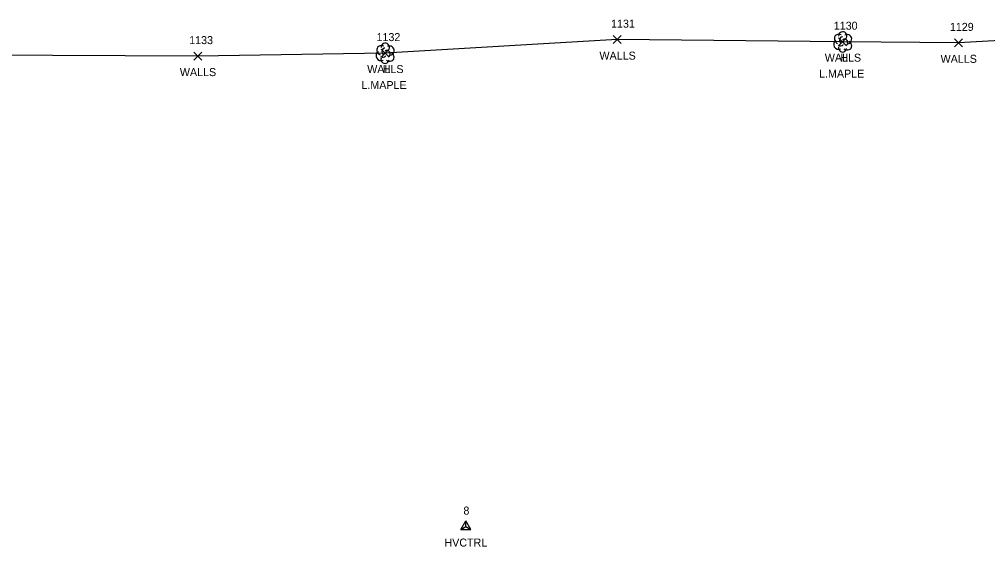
# Model space of a CAD drawing. Extents: x 1519347 to 1522636, y 378779 to 379832.
# Drawn here: x 1521885.3 to 1522127.4, y 378778.8 to 378910.7 of the extents above; entities that cross this region are included whole.
import ezdxf

# ---------------------------------------------------------------- set-up
doc = ezdxf.new("R2010")
doc.units = 0
for name, color, linetype in [('C_A', 7, 'Continuous'), ('C_I', 7, 'Continuous'), ('CPSM', 7, 'Continuous'), ('L_A', 7, 'Continuous'), ('L_C', 7, 'Continuous'), ('L_I', 7, 'Continuous'), ('L_TIC', 7, 'Continuous'), ('LTD', 7, 'Continuous'), ('LWS', 7, 'Continuous')]:
    doc.layers.add(name, color=color, linetype=linetype)

msp = doc.modelspace()

# ---------------------------------------------------------------- linework, layer by layer
at = {"layer": 'CPSM'}
for p, q in [((1521995.64, 378783.1), (1521996.89, 378785.27)), ((1521995.64, 378783.1), (1521996.89, 378783.82)), ((1521998.14, 378783.1), (1521996.89, 378785.27)), ((1521996.89, 378783.82), (1521996.89, 378785.27)), ((1521996.89, 378783.82), (1521996.89, 378783.82)), ((1521996.89, 378783.82), (1521998.14, 378783.1)), ((1521995.64, 378783.1), (1521998.14, 378783.1))]:
    msp.add_line(p, q, dxfattribs=at)
at = {"layer": 'L_TIC'}
for points in [[(1522033.79, 378904.64), (1522035.79, 378906.64)], [(1522035.79, 378904.64), (1522033.79, 378906.64)], [(1522090.12, 378904.13), (1522092.12, 378906.13)], [(1522092.12, 378904.13), (1522090.12, 378906.13)], [(1522119.07, 378903.84), (1522121.07, 378905.84)], [(1522121.07, 378903.84), (1522119.07, 378905.84)], [(1521928.9, 378900.52), (1521930.9, 378902.52)], [(1521930.9, 378900.52), (1521928.9, 378902.52)], [(1521975.72, 378901.28), (1521977.72, 378903.28)], [(1521977.72, 378901.28), (1521975.72, 378903.28)]]:
    msp.add_lwpolyline(points, dxfattribs=at)
at = {"layer": 'LTD'}
for p, q in [((1522091.12, 378905.13), (1522091.12, 378905.13)), ((1522091.12, 378905.13), (1522091.12, 378905.13)), ((1521976.72, 378902.28), (1521976.72, 378902.28)), ((1521976.72, 378902.28), (1521976.72, 378902.28))]:
    msp.add_line(p, q, dxfattribs=at)
for centre in [(1522091.16, 378906.56), (1521976.77, 378903.72)]:
    msp.add_arc(centre, 1.05, 335.5272, 180.9563, dxfattribs=at)
for centre, major_axis, ratio, start_param, end_param in [((1522090.33, 378905.79), (1.21, -0.51), 0.895232, 1.570796, 4.712389), ((1522092.16, 378905.71), (-1.14, -0.48), 0.949671, 1.570796, 4.712389), ((1522090.03, 378904.42), (0.58, -1.04), 0.959034, 3.141593, 6.283185), ((1522090.91, 378905.58), (-0.208, -0.792), 0.645439, 3.141593, 6.283185), ((1522091.62, 378904.96), (-0.5, 0.667), 0.989748, 3.141593, 6.283185), ((1522092.12, 378904.29), (-1.09, 0.79), 0.841452, 1.570796, 4.712389), ((1521975.64, 378901.57), (0.58, -1.04), 0.959034, 3.141593, 6.283185), ((1521975.93, 378902.95), (1.21, -0.51), 0.895232, 1.570796, 4.712389), ((1521976.51, 378902.74), (-0.208, -0.792), 0.645439, 3.141593, 6.283185), ((1521977.22, 378902.12), (-0.5, 0.667), 0.989748, 3.141593, 6.283185), ((1521977.72, 378901.45), (-1.09, 0.79), 0.841452, 1.570796, 4.712389), ((1521977.76, 378902.87), (-1.14, -0.48), 0.949671, 1.570796, 4.712389), ((1522091.12, 378903.63), (0.26, 1.06), 0.942809, 1.570796, 4.712389), ((1522090.66, 378904.38), (-0.625, -0.083), 0.423636, 0, 3.141593), ((1521976.72, 378900.78), (0.26, 1.06), 0.942809, 1.570796, 4.712389), ((1521976.26, 378901.53), (-0.625, -0.083), 0.423636, 0, 3.141593)]:
    msp.add_ellipse(centre, major_axis=major_axis, ratio=ratio, start_param=start_param, end_param=end_param, dxfattribs=at)
at = {"layer": 'LWS'}
msp.add_lwpolyline([(1522445.31, 378910.72), (1522401.54, 378910.43), (1522348.21, 378909.74), (1522295.88, 378908.39), (1522245.08, 378908.42), (1522202.2, 378906.68), (1522157.16, 378906.96), (1522120.07, 378904.84), (1522091.12, 378905.13), (1522034.79, 378905.64), (1521976.72, 378902.28), (1521929.9, 378901.52), (1521875.34, 378901.77), (1521835.92, 378899.64), (1521789.94, 378904.13), (1521732.75, 378904.41), (1521692.11, 378903.65), (1521648.67, 378903.93), (1521616.94, 378904.79), (1521567.34, 378904.32)], dxfattribs=at)

# ---------------------------------------------------------------- texts
at = {"layer": 'C_A'}
msp.add_text('HVCTRL', height=2, dxfattribs=at).set_placement((1521991.58, 378778.82))
at = {"layer": 'C_I'}
msp.add_text('8', height=2, dxfattribs=at).set_placement((1521996.32, 378786.82))
at = {"layer": 'L_A'}
for s, p in [('WALLS', (1522030.33, 378900.64)), ('WALLS', (1522086.66, 378900.13)), ('H', (1522090.55, 378900.13)), ('WALLS', (1522115.61, 378899.84)), ('WALLS', (1521925.44, 378896.52)), ('WALLS', (1521972.27, 378897.28)), ('H', (1521976.16, 378897.28))]:
    msp.add_text(s, height=2, dxfattribs=at).set_placement(p)
at = {"layer": 'L_C'}
for p in [(1522085.23, 378896.13), (1521970.83, 378893.28)]:
    msp.add_text('L.MAPLE', height=2, dxfattribs=at).set_placement(p)
at = {"layer": 'L_I'}
for s, p in [('1131', (1522033.23, 378908.64)), ('1130', (1522088.91, 378908.13)), ('1130', (1522088.91, 378908.13)), ('1129', (1522117.93, 378907.84)), ('1132', (1521974.6, 378905.28)), ('1132', (1521974.6, 378905.28)), ('1133', (1521927.77, 378904.52))]:
    msp.add_text(s, height=2, dxfattribs=at).set_placement(p)

doc.saveas('drawing.dxf')
